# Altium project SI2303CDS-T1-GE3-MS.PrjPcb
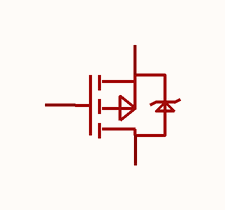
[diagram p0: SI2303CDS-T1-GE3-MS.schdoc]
1 sheet, 1 parts. Net scope: global (net labels, ports and power ports of the same name join across sheets).

## Sheet SI2303CDS-T1-GE3-MS.schdoc
size 127 x 101 mm

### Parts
Q?  si2303cds-t1-ge3-ms  [SOT-23-3_L2.9-W1.3-P1.90-LS2.4-BR]  (value not drawn)

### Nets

Not connected (* = marked no-connect by the designer): Q? 1(G) 2(S) 3(D)

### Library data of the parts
Q? = si2303cds-t1-ge3-ms: 数量:1个P沟道;漏源电压(Vdss):30V;连续漏极电流(Id):3A;导通电阻(RDS(on)):150mΩ@10V;耗散功率(Pd):1.56W;阈值电压(Vgs(th)):1.5V;; Manufacturer: MSKSEMI(美森科); AddInBom: yes; ModelId: c62791f0466c4ae2a892c056b845b0ca; ModelName: SOT-23-3P_L2.9-W1.3-H1.0-LS2.4-P0.95; ModelTransform: 98.425,114.173,0,180,0,0,0.0005,-0.0005,0; Number: 1个P沟道; Drain to Source Voltage: 30V; Current - Continuous Drain(Id): 3A; Pd - Power Dissipation: 1.56W; Gate Threshold Voltage (Vgs(th)): 1.5V; Gate Charge(Qg): 2.5nC@4.5V; Input Capacitance(Ciss): 226pF; Reverse Transfer Capacitance (Crss@Vds): 29pF; Type: P沟道; Output Capacitance(Coss): 39pF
